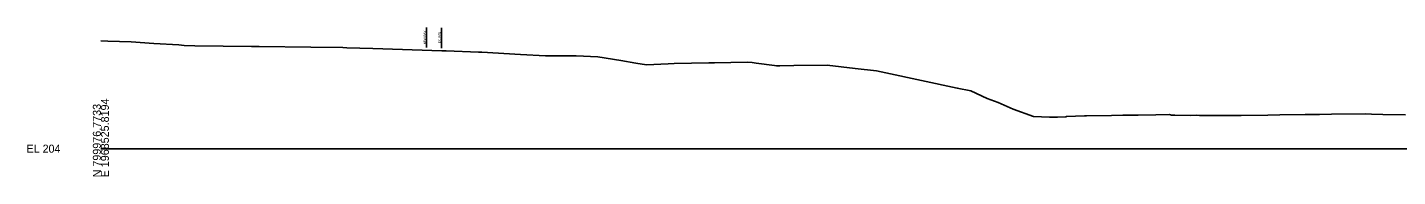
# Model space of a CAD drawing. Extents: x 1979833 to 1982361, y 790388 to 810009.
# Drawn here: x 1979832.9 to 1980312.1, y 804388 to 804440 of the extents above; entities that cross this region are included whole.
import ezdxf

# ---------------------------------------------------------------- set-up
doc = ezdxf.new("R2010")
doc.units = 0
for name, color, linetype in [('Default', 7, 'Continuous'), ('RD_GPK_XS_Cell', 7, 'Continuous'), ('RD_XS_ExGround', 7, 'Continuous'), ('RD_XS_ExRW', 7, 'Continuous'), ('RD_XS_NewRW', 7, 'Continuous')]:
    doc.layers.add(name, color=color, linetype=linetype)

msp = doc.modelspace()

# ---------------------------------------------------------------- linework, layer by layer
at = {"layer": 'RD_GPK_XS_Cell'}
msp.add_line((1979858.57, 804397.73), (1980358.57, 804397.73), dxfattribs=at)
at = {"layer": 'RD_XS_ExGround'}
msp.add_lwpolyline([(1979858.57, 804435.35), (1979861.06, 804435.25), (1979869.17, 804434.95), (1979877.15, 804434.35), (1979885.8, 804433.91), (1979887.76, 804433.73), (1979891.44, 804433.54), (1979911.27, 804433.36), (1979912.65, 804433.35), (1979913.92, 804433.34), (1979931.98, 804433.09), (1979943.16, 804432.95), (1979944.62, 804432.88), (1979953.68, 804432.59), (1979977.89, 804431.78), (1979979.38, 804431.79), (1979990.71, 804431.39), (1979991.88, 804431.35), (1980005.37, 804430.5), (1980014.05, 804430.11), (1980024.81, 804430.14), (1980032.44, 804429.79), (1980040.41, 804428.49), (1980045.64, 804427.54), (1980049.46, 804426.92), (1980056.99, 804427.35), (1980059.07, 804427.45), (1980071.27, 804427.61), (1980072, 804427.62), (1980073.16, 804427.64), (1980084.68, 804427.92), (1980086.37, 804427.78), (1980087.82, 804427.59), (1980094.18, 804426.69), (1980094.92, 804426.59), (1980096.05, 804426.6), (1980100.92, 804426.7), (1980112.58, 804426.79), (1980122.43, 804425.73), (1980129.92, 804424.82), (1980133.14, 804424.11), (1980158.14, 804418.87), (1980162.89, 804417.85), (1980168.61, 804415.24), (1980172.43, 804413.79), (1980177.63, 804411.52), (1980184.76, 804408.95), (1980190.34, 804408.74), (1980192.76, 804408.73), (1980193.23, 804408.74), (1980196.15, 804408.84), (1980196.34, 804408.96), (1980202.67, 804409.14), (1980203.27, 804409.16), (1980212.06, 804409.3), (1980215.99, 804409.36), (1980221.45, 804409.46), (1980227.6, 804409.54), (1980232.34, 804409.62), (1980233.06, 804409.41), (1980234.17, 804409.41), (1980239.56, 804409.28), (1980241.86, 804409.36), (1980242.8, 804409.32), (1980244.88, 804409.27), (1980246.34, 804409.25), (1980246.6, 804409.32), (1980250.89, 804409.31), (1980251.89, 804409.31), (1980257.47, 804409.32), (1980266.76, 804409.43), (1980270.97, 804409.49), (1980279.87, 804409.6), (1980284.79, 804409.69), (1980288.98, 804409.73), (1980300.98, 804409.85), (1980302.98, 804409.8), (1980306.99, 804409.7), (1980314.86, 804409.52)], dxfattribs=at)
at = {"layer": 'RD_XS_ExRW'}
msp.add_line((1979977.66, 804432.79), (1979977.66, 804439.79), dxfattribs=at)
at = {"layer": 'RD_XS_NewRW'}
msp.add_line((1979972.52, 804432.96), (1979972.52, 804439.96), dxfattribs=at)

# ---------------------------------------------------------------- texts
at = {"layer": 'Default'}
msp.add_text('-', height=0.0001, dxfattribs=at).set_placement((1979858.57, 804397.73))
at = {"layer": 'RD_GPK_XS_Cell'}
for s, p in [('N 799976.7733', (1979858.57, 804387.73)), ('E 1968525.8194', (1979861.37, 804387.73))]:
    msp.add_text(s, height=2.8, rotation=90, dxfattribs=at).set_placement(p)
msp.add_text('EL 204', height=2.8, dxfattribs=at).set_placement((1979832.57, 804396.33))
at = {"layer": 'RD_XS_ExRW'}
msp.add_text('EX. R/W ', height=0.75, rotation=90, dxfattribs=at).set_placement((1979977.4, 804434.47))
at = {"layer": 'RD_XS_NewRW'}
msp.add_text('NEW R/W ', height=0.75, rotation=90, dxfattribs=at).set_placement((1979972.27, 804434.11))

doc.saveas('drawing.dxf')
